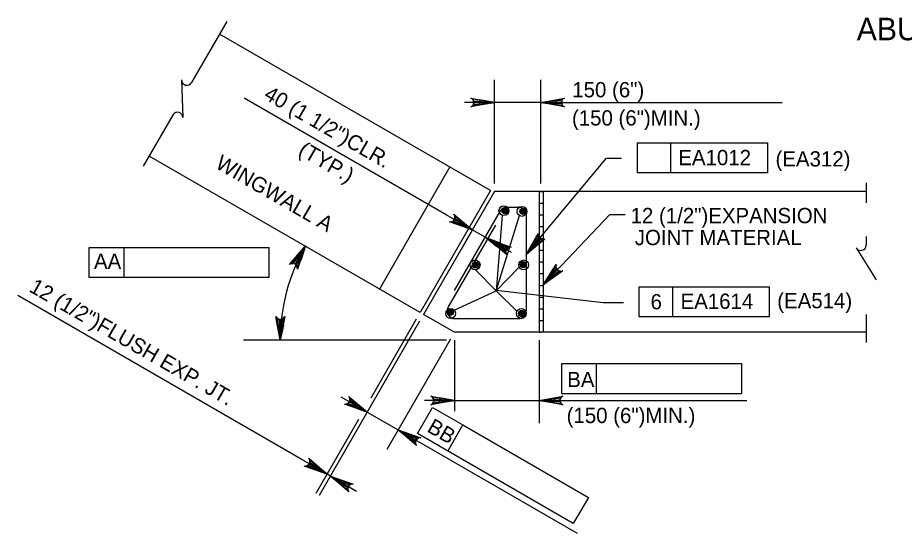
# Model space of a CAD drawing. Extents: x 638340 to 640241, y 295465 to 298435.
# Drawn here: x 638529.6 to 638703.7, y 297536.3 to 297637.6 of the extents above; entities that cross this region are included whole.
import ezdxf

# ---------------------------------------------------------------- set-up
doc = ezdxf.new("R2010")
doc.units = 0
for name, color, linetype in [('10', 7, 'Continuous'), ('3', 7, 'Continuous'), ('4', 7, 'Continuous'), ('5', 7, 'Continuous')]:
    doc.layers.add(name, color=color, linetype=linetype)

msp = doc.modelspace()

# ---------------------------------------------------------------- linework, layer by layer
at = {"layer": '10'}
for p, q in [((638622.42, 297603.67), (638569.19, 297634.4)), ((638608.58, 297579.69), (638555.35, 297610.42)), ((638614.43, 297608.28), (638600.58, 297584.3)), ((638622.42, 297603.67), (638608.58, 297579.69)), ((638623.2, 297603.48), (638609.24, 297579.31)), ((638696.2, 297603.48), (638623.2, 297603.48)), ((638631.97, 297603.48), (638631.97, 297575.8)), ((638632.74, 297603.48), (638632.74, 297575.8)), ((638615.32, 297575.8), (638609.24, 297579.31)), ((638696.2, 297575.8), (638615.32, 297575.8))]:
    msp.add_line(p, q, dxfattribs=at)
at = {"layer": '3'}
for p, q in [((638623.2, 297605.02), (638623.2, 297625.38)), ((638632.26, 297605.02), (638632.26, 297625.38)), ((638613.72, 297598.86), (638574.04, 297621.77)), ((638623.2, 297620.95), (638617.3, 297620.95)), ((638632.26, 297620.95), (638623.2, 297620.95)), ((638632.26, 297620.95), (638679.66, 297620.95)), ((638651.24, 297613.05), (638676.78, 297613.05)), ((638651.24, 297607.15), (638651.24, 297613.05)), ((638657.83, 297607.15), (638657.83, 297613.05)), ((638676.78, 297613.05), (638676.78, 297607.15)), ((638629.43, 297591.06), (638645.21, 297609.99)), ((638645.21, 297609.99), (638648.16, 297609.99)), ((638676.78, 297607.15), (638651.24, 297607.15)), ((638618.83, 297595.91), (638613.72, 297598.86)), ((638632.74, 297585.11), (638645.87, 297598.92)), ((638645.87, 297598.92), (638648.82, 297598.92)), ((638618.59, 297595.49), (638616.61, 297592.07)), ((638543.61, 297592.48), (638550.46, 297592.48)), ((638543.61, 297586.57), (638543.61, 297592.48)), ((638550.46, 297586.57), (638550.46, 297592.48)), ((638550.46, 297592.48), (638578.92, 297592.48)), ((638578.92, 297586.57), (638578.92, 297592.48)), ((638578.92, 297586.57), (638543.61, 297586.57)), ((638651.58, 297584.73), (638677.12, 297584.73)), ((638651.58, 297578.83), (638651.58, 297584.73)), ((638658.18, 297578.83), (638658.18, 297584.73)), ((638677.12, 297584.73), (638677.12, 297578.83)), ((638585.19, 297550.9), (638529.55, 297583.02)), ((638644.56, 297581.67), (638648.51, 297581.67)), ((638677.12, 297578.83), (638651.58, 297578.83)), ((638608.47, 297577.97), (638588.76, 297543.72)), ((638607.81, 297578.36), (638598.87, 297562.84)), ((638613.79, 297574.26), (638573.88, 297574.26)), ((638614.55, 297574.46), (638602.03, 297552.78)), ((638615.32, 297574.26), (638615.32, 297560.27)), ((638631.97, 297574.26), (638631.97, 297557.97)), ((638636.38, 297563.73), (638636.38, 297569.64)), ((638636.38, 297569.64), (638643.22, 297569.64)), ((638643.22, 297563.73), (638643.22, 297569.64)), ((638643.22, 297569.64), (638671.68, 297569.64)), ((638671.68, 297569.64), (638671.68, 297563.73)), ((638595.61, 297561.6), (638593.06, 297563.08)), ((638671.68, 297563.73), (638636.38, 297563.73)), ((638612.37, 297562.4), (638609.42, 297562.4)), ((638615.32, 297562.4), (638639.68, 297562.4)), ((638634.92, 297562.4), (638637.87, 297562.4)), ((638637.87, 297562.4), (638672.74, 297562.4)), ((638598.17, 297560.12), (638604.25, 297556.61)), ((638608.09, 297555.89), (638611.04, 297561.01)), ((638611.04, 297561.01), (638616.97, 297557.59)), ((638596.45, 297558.63), (638588.09, 297544.11)), ((638614.02, 297552.47), (638616.97, 297557.59)), ((638616.97, 297557.59), (638641.62, 297543.36)), ((638606.8, 297555.14), (638609.36, 297553.66)), ((638638.66, 297538.24), (638608.09, 297555.89)), ((638609.36, 297553.66), (638639.42, 297536.31)), ((638587.75, 297549.42), (638585.19, 297550.9)), ((638590.97, 297547.56), (638590.31, 297547.94)), ((638593.53, 297546.08), (638596.08, 297544.61)), ((638641.62, 297543.36), (638638.66, 297538.24))]:
    msp.add_line(p, q, dxfattribs=at)
for points in [[(638623.2, 297620.95), (638618.54, 297620.08), (638618.9, 297620.33), (638619.08, 297620.64), (638619.14, 297620.95), (638619.08, 297621.26), (638618.9, 297621.58), (638618.54, 297621.82), (638623.2, 297620.95), (638618.9, 297621.58), (638619.08, 297621.26), (638623.2, 297620.95), (638619.14, 297620.95), (638619.08, 297620.64), (638623.2, 297620.95), (638618.9, 297620.33)], [(638632.26, 297620.95), (638636.92, 297621.82), (638636.56, 297621.58), (638636.38, 297621.26), (638636.32, 297620.95), (638636.38, 297620.64), (638636.56, 297620.33), (638636.92, 297620.08), (638632.26, 297620.95), (638636.56, 297620.33), (638636.38, 297620.64), (638632.26, 297620.95), (638636.32, 297620.95), (638636.38, 297621.26), (638632.26, 297620.95), (638636.56, 297621.58)], [(638618.83, 297595.91), (638614.35, 297597.48), (638614.79, 297597.52), (638615.11, 297597.7), (638615.31, 297597.94), (638615.42, 297598.24), (638615.42, 297598.6), (638615.23, 297599), (638618.83, 297595.91), (638615.42, 297598.6), (638615.42, 297598.24), (638618.83, 297595.91), (638615.31, 297597.94), (638615.11, 297597.7), (638618.83, 297595.91), (638614.79, 297597.52)], [(638629.43, 297591.06), (638631.74, 297595.2), (638631.7, 297594.77), (638631.82, 297594.42), (638632.03, 297594.18), (638632.3, 297594.02), (638632.66, 297593.97), (638633.08, 297594.08), (638629.43, 297591.06), (638632.66, 297593.97), (638632.3, 297594.02), (638629.43, 297591.06), (638632.03, 297594.18), (638631.82, 297594.42), (638629.43, 297591.06), (638631.7, 297594.77)], [(638586.03, 297592.7), (638584.47, 297588.23), (638584.43, 297588.66), (638584.25, 297588.98), (638584.01, 297589.18), (638583.71, 297589.29), (638583.35, 297589.29), (638582.95, 297589.1), (638586.03, 297592.7), (638583.35, 297589.29), (638583.71, 297589.29), (638586.03, 297592.7), (638584.01, 297589.18), (638584.25, 297588.98), (638586.03, 297592.7), (638584.43, 297588.66)], [(638632.74, 297585.11), (638635.32, 297589.09), (638635.25, 297588.66), (638635.35, 297588.31), (638635.54, 297588.05), (638635.8, 297587.88), (638636.16, 297587.8), (638636.58, 297587.89), (638632.74, 297585.11), (638636.16, 297587.8), (638635.8, 297587.88), (638632.74, 297585.11), (638635.54, 297588.05), (638635.35, 297588.31), (638632.74, 297585.11), (638635.25, 297588.66)], [(638581.11, 297574.26), (638580.23, 297578.92), (638580.48, 297578.56), (638580.8, 297578.37), (638581.11, 297578.32), (638581.42, 297578.37), (638581.73, 297578.56), (638581.98, 297578.92), (638581.11, 297574.26), (638581.73, 297578.56), (638581.42, 297578.37), (638581.11, 297574.26), (638581.11, 297578.32), (638580.8, 297578.37), (638581.11, 297574.26), (638580.48, 297578.56)], [(638598.19, 297560.11), (638593.72, 297561.69), (638594.15, 297561.72), (638594.47, 297561.9), (638594.67, 297562.14), (638594.78, 297562.44), (638594.78, 297562.81), (638594.59, 297563.2), (638598.19, 297560.11), (638594.78, 297562.81), (638594.78, 297562.44), (638598.19, 297560.11), (638594.67, 297562.14), (638594.47, 297561.9), (638598.19, 297560.11), (638594.15, 297561.72)], [(638615.32, 297562.4), (638610.66, 297561.53), (638611.02, 297561.77), (638611.21, 297562.09), (638611.26, 297562.4), (638611.21, 297562.71), (638611.02, 297563.02), (638610.66, 297563.27), (638615.32, 297562.4), (638611.02, 297563.02), (638611.21, 297562.71), (638615.32, 297562.4), (638611.26, 297562.4), (638611.21, 297562.09), (638615.32, 297562.4), (638611.02, 297561.77)], [(638631.97, 297562.4), (638636.63, 297563.27), (638636.27, 297563.02), (638636.09, 297562.71), (638636.03, 297562.4), (638636.09, 297562.09), (638636.27, 297561.77), (638636.63, 297561.53), (638631.97, 297562.4), (638636.27, 297561.77), (638636.09, 297562.09), (638631.97, 297562.4), (638636.03, 297562.4), (638636.09, 297562.71), (638631.97, 297562.4), (638636.27, 297563.02)], [(638604.25, 297556.61), (638608.72, 297555.04), (638608.29, 297555.01), (638607.97, 297554.83), (638607.77, 297554.58), (638607.66, 297554.29), (638607.66, 297553.92), (638607.85, 297553.53), (638604.25, 297556.61), (638607.66, 297553.92), (638607.66, 297554.29), (638604.25, 297556.61), (638607.77, 297554.58), (638607.97, 297554.83), (638604.25, 297556.61), (638608.29, 297555.01)], [(638590.3, 297547.95), (638585.83, 297549.52), (638586.26, 297549.56), (638586.58, 297549.74), (638586.78, 297549.98), (638586.89, 297550.28), (638586.89, 297550.64), (638586.7, 297551.04), (638590.3, 297547.95), (638586.89, 297550.64), (638586.89, 297550.28), (638590.3, 297547.95), (638586.78, 297549.98), (638586.58, 297549.74), (638590.3, 297547.95), (638586.26, 297549.56)], [(638590.98, 297547.55), (638595.46, 297545.98), (638595.02, 297545.95), (638594.7, 297545.77), (638594.5, 297545.53), (638594.39, 297545.23), (638594.4, 297544.86), (638594.58, 297544.47), (638590.98, 297547.55), (638594.4, 297544.86), (638594.39, 297545.23), (638590.98, 297547.55), (638594.5, 297545.53), (638594.7, 297545.77), (638590.98, 297547.55), (638595.02, 297545.95)]]:
    msp.add_lwpolyline(points, dxfattribs=at)
for points in [[(638620.25, 297621.44), (638620.25, 297620.46), (638623.2, 297620.95)], [(638635.21, 297621.44), (638635.21, 297620.46), (638632.26, 297620.95)], [(638616.52, 297597.81), (638616.03, 297596.96), (638618.83, 297595.91)], [(638585.13, 297589.92), (638584.26, 297590.38), (638586.07, 297592.76)], [(638580.73, 297577.23), (638581.72, 297577.19), (638581.11, 297574.26)], [(638595.86, 297562.03), (638595.37, 297561.17), (638598.17, 297560.12)], [(638612.37, 297562.89), (638612.37, 297561.91), (638615.32, 297562.4)], [(638634.92, 297562.89), (638634.92, 297561.91), (638631.97, 297562.4)], [(638607.05, 297555.56), (638606.56, 297554.71), (638604.25, 297556.61)], [(638587.99, 297549.85), (638587.5, 297548.99), (638590.31, 297547.94)], [(638593.77, 297546.51), (638593.28, 297545.66), (638590.97, 297547.56)]]:
    msp.add_lwpolyline(points, close=True, dxfattribs=at)
msp.add_arc((638618.12, 297574.26), 37.01, 150.1038, 180, dxfattribs=at)
at = {"layer": '4'}
for p, q in [((638570.62, 297636.88), (638563.69, 297624.88)), ((638561.7, 297625.41), (638561.99, 297617.99)), ((638560.05, 297618.57), (638554.21, 297608.45)), ((638696.2, 297605.13), (638696.2, 297601.23)), ((638696.2, 297594.6), (638696.2, 297592.94)), ((638694.21, 297592.4), (638698.16, 297586.12)), ((638696.2, 297579.28), (638696.2, 297573.78))]:
    msp.add_line(p, q, dxfattribs=at)
for centre, start, end in [((638562.77, 297625.41), 180, 330), ((638560.92, 297617.95), 2.1328, 144.6714), ((638695.13, 297592.94), 210, 0)]:
    msp.add_arc(centre, 1.07, start, end, dxfattribs=at)
at = {"layer": '5'}
for p, q in [((638631.97, 297603.48), (638632.74, 297603.48)), ((638624.31, 297599.63), (638615.29, 297584)), ((638625.64, 297600.39), (638627.89, 297600.39)), ((638631.97, 297601.17), (638632.74, 297601.17)), ((638624.72, 297598.77), (638623.54, 297583.91)), ((638623.54, 297583.91), (638628.1, 297598.71)), ((638629.43, 297598.86), (638629.43, 297580.02)), ((638631.97, 297598.87), (638632.74, 297598.87)), ((638623.37, 297596.85), (638614.1, 297580.79)), ((638631.97, 297596.56), (638632.74, 297596.56)), ((638621.33, 297594.47), (638618.83, 297595.91)), ((638621.99, 297594.08), (638626.44, 297591.51)), ((638631.97, 297594.25), (638632.74, 297594.25)), ((638631.97, 297591.94), (638632.74, 297591.95)), ((638631.97, 297589.64), (638632.74, 297589.64)), ((638619.44, 297588.08), (638623.54, 297583.91)), ((638623.54, 297583.91), (638628.06, 297588.57)), ((638631.97, 297587.33), (638632.74, 297587.33)), ((638615.29, 297580.12), (638623.54, 297583.91)), ((638623.54, 297584.08), (638644.56, 297581.67)), ((638623.54, 297583.91), (638627.6, 297579.92)), ((638631.97, 297585.02), (638632.74, 297585.02)), ((638631.97, 297582.72), (638632.74, 297582.72)), ((638631.97, 297580.41), (638632.74, 297580.41)), ((638615.43, 297578.48), (638627.89, 297578.48)), ((638631.97, 297578.1), (638632.74, 297578.1)), ((638631.97, 297575.8), (638632.19, 297575.8))]:
    msp.add_line(p, q, dxfattribs=at)
msp.add_lwpolyline([(638624.13, 297593.42), (638623.64, 297592.56), (638621.33, 297594.47)], close=True, dxfattribs=at)
msp.add_lwpolyline([(638621.99, 297594.08), (638626.47, 297592.51), (638626.03, 297592.47), (638625.72, 297592.29), (638625.51, 297592.05), (638625.4, 297591.75), (638625.41, 297591.39), (638625.59, 297590.99), (638621.99, 297594.08), (638625.41, 297591.39), (638625.4, 297591.75), (638621.99, 297594.08), (638625.51, 297592.05), (638625.72, 297592.29), (638621.99, 297594.08), (638626.03, 297592.47)], dxfattribs=at)
for centre, radius in [((638625.03, 297599.68), 0.962), ((638625.24, 297599.7), 0.625), ((638625.24, 297599.7), 0.469), ((638625.24, 297599.7), 0.313), ((638625.24, 297599.7), 0.156), ((638628.58, 297599.54), 0.962), ((638628.78, 297599.56), 0.625), ((638628.78, 297599.56), 0.469), ((638628.78, 297599.56), 0.313), ((638628.78, 297599.56), 0.156), ((638619.38, 297589.04), 0.962), ((638619.47, 297589.02), 0.625), ((638619.47, 297589.02), 0.469), ((638619.47, 297589.02), 0.313), ((638619.47, 297589.02), 0.156), ((638628.9, 297589.04), 0.962), ((638628.85, 297589.09), 0.625), ((638628.85, 297589.09), 0.469), ((638628.85, 297589.09), 0.313), ((638628.85, 297589.09), 0.156), ((638614.56, 297579.49), 0.962), ((638628.45, 297579.49), 0.962), ((638614.5, 297579.71), 0.625), ((638614.5, 297579.71), 0.469), ((638614.5, 297579.71), 0.313), ((638614.5, 297579.71), 0.156), ((638628.54, 297579.47), 0.625), ((638628.54, 297579.47), 0.469), ((638628.54, 297579.47), 0.313), ((638628.54, 297579.47), 0.156)]:
    msp.add_circle(centre, radius, dxfattribs=at)
for centre, start, end in [((638625.64, 297598.86), 90, 150), ((638627.89, 297598.86), 0, 90), ((638615.43, 297580.02), 150, 270), ((638627.89, 297580.02), 270, 0)]:
    msp.add_arc(centre, 1.54, start, end, dxfattribs=at)

# ---------------------------------------------------------------- texts
at = {"layer": '3'}
for s, height, p in [('ABUTMENT PLAN', 4.4294, (638694.33, 297633.17)), ('150 (6")', 3, (638638.46, 297621.96)), ('(150 (6")MIN.)', 3.0001, (638638.4, 297616.42)), ('EA1012', 3, (638659.29, 297608.63)), ('(EA312)', 3, (638678.38, 297608.37)), ('12 (1/2")EXPANSION', 3.0001, (638649.92, 297597.23)), ('JOINT MATERIAL', 3.0001, (638650.74, 297592.92)), ('AA', 3, (638544.53, 297588.25)), ('6', 3, (638653.84, 297580.31)), ('EA1614', 3, (638659.73, 297580.4)), ('(EA514)', 3, (638678.72, 297580.51)), ('BA', 3, (638637.47, 297565.02)), ('(150 (6")MIN.)', 3.0001, (638637.36, 297557.96))]:
    msp.add_text(s, height=height, dxfattribs=at).set_placement(p)
for s, height, p in [(' 40 (1 1/2")CLR.', 3.0001, (638576.71, 297622.35)), ('(TYP.)', 3, (638584.44, 297610.83)), ('WINGWALL A', 3, (638568.15, 297608.21)), ('12 (1/2")FLUSH EXP. JT.', 3.0001, (638531.59, 297583.93)), ('BB', 3, (638609.74, 297556.4))]:
    msp.add_text(s, height=height, rotation=330, dxfattribs=at).set_placement(p)

doc.saveas('drawing.dxf')
